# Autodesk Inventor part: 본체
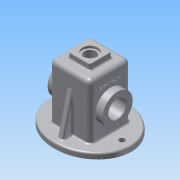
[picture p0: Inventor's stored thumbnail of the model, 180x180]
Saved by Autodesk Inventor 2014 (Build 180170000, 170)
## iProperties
Created: 2017-07
Part Number: 본체
Material: 알루미늄 6061
Document SubType Name: Modeling
Designer: 406-12
Density: 2.71 g/cm^3
Appearance: 알루미늄 - 평지
Mass: 890.222 g
Surface Area: 996.654 cm^2
Volume: 328.495 cm^3
Author: 406-12
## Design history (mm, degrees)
sketch "스케치1"
  geometry: 2 further points; 1 other entity
  constraints: 1 coincident, 2 other
extrude "돌출1" new body sketch "스케치1" distance "d0" = 10; taper "d1" = 0 deg
sketch "스케치2"
  geometry: L1 (0, 10)-(0, 110); L2 (37, 10)-(37, 110); L3 (-37, 10)-(-37, 110); L4 (-74.587, 0)-(99.979, 0); L5 (-37, 110)-(37, 110); L6 (65, 10)-(65, 0) reference; L7 (65, 0)-(-65, 0) reference; L8 (-65, 0)-(-65, 10) reference; L9 (-65, 10)-(65, 10) reference; L10 (-37, 10)-(37, 10); 1 further point
  constraints: 12 end point, 3 parallel, 2 midpoint, 2 point on line
  dimensions: "d2" = 37 distance between parallel lines of L1 L3; "d3" = 37 distance between parallel lines of L2 L1; "d4" = 110 distance between parallel lines of L5 L4
extrude "돌출2" join sketch "스케치2" stored distance "d5" = 74; taper "d6" = 0 deg
sketch "스케치3"
  geometry: L1 (-75, 0)-(-75, 10) reference; L2 (-75, 10)-(-37, 10) reference; L3 (-37, 10)-(-37, 110) reference; L4 (-37, 110)-(37, 110) reference; L5 (37, 110)-(37, 10) reference; L6 (37, 10)-(75, 10) reference; L7 (75, 10)-(75, 0) reference; L8 (75, 0)-(-75, 0) reference; L9 (0, 110)-(0, 120); L10 (-20, 110)-(20, 110); L11 (-19.125, 120)-(19.125, 120); L12 (-20, 110)-(-19.125, 120); L13 (20, 110)-(19.125, 120); 3 further points
  constraints: 10 end point, 2 midpoint, 1 parallel, 1 symmetric about line
  dimensions: "d9" = 10 distance between parallel lines of L4 L11; "d13" = 5 deg angle of L12 L3
extrude "돌출3" join sketch "스케치3" stored distance "d14" = 40; taper "d15" = 0 deg
sketch "스케치4"
  geometry: L1 (-75, 0)-(-75, 10) reference; L2 (-75, 10)-(-37, 10) reference; L3 (-37, 10)-(-37, 110) reference; L4 (-37, 110)-(-20, 110) reference; L5 (-20, 110)-(-19.125, 120) reference; L6 (-19.125, 120)-(19.125, 120) reference; L7 (19.125, 120)-(20, 110) reference; L8 (20, 110)-(37, 110) reference; L9 (37, 110)-(37, 10) reference; L10 (37, 10)-(75, 10) reference; L11 (75, 10)-(75, 0) reference; L12 (75, 0)-(-75, 0) reference; L13 (-32, 0)-(32, 0); L14 (-32, 0)-(-32, 105); L15 (0, 0)-(0, 105); L16 (32, 0)-(32, 105); L17 (-32, 105)-(32, 105); L18 (-32, 0)-(32, 0)
  constraints: 12 end point, 3 parallel, 1 midpoint
extrude "돌출4" cut sketch "스케치4" stored distance "d19" = 64; taper "d20" = 0 deg
node "작업 평면1"
sketch "스케치7"
  geometry: L1 (-10, 48.448)-(0, 48.448) reference; L2 (0, 48.448)-(0, -48.448) reference; L3 (0, -48.448)-(-10, -48.448) reference; L4 (-10, -48.448)-(-10, 48.448) reference; L5 (0, 0)-(-55, 0); C1 r 27.5 at (-55, 0)
  constraints: 2 end point, 1 centre point, 1 coincident
extrude "돌출5" join sketch "스케치7" stored distance "d22" = 64; taper "d23" = 0 deg
sketch "스케치8"
  geometry: L1 (0, 32)-(55, 32); C1 r 27.5 at (55, 32)
  constraints: 2 end point, 1 centre point, 1 coincident
extrude "돌출6" join sketch "스케치8" distance "d24" = 7; taper "d25" = 0 deg
chamfer "모따기1" distance "d26" = 7; stored, may be unused: second distance "d27" = 2, angle "d28" = 135 deg
hole "구멍1" diameter "d31" = 32; stored, may be unused: countersink angle "d35" = 90 deg, drill point angle "d37" = 0 deg; dims "d29" = 10, "d30" = 10, "d32" = 6, "d33" = 4, "d34" = 2, "d36" = 25
sketch "스케치10"
  geometry: 5 further points
hole "구멍2" sketch "스케치10" at (-22.5, 0), (0, -22.5), (22.5, 0), (0, 22.5) diameter "d38" = 3.242; stored, may be unused: countersink angle "d42" = 90 deg, drill point angle "d44" = 118 deg; dims "d39" = 8, "d40" = 4, "d41" = 2, "d43" = 10
sketch "스케치11"
  geometry: 1 further point
hole "구멍3" sketch "스케치11" at (19.125, -20) diameter "d45" = 21; stored, may be unused: countersink angle "d49" = 90 deg, drill point angle "d51" = 118 deg; dims "d46" = 8, "d47" = 28, "d48" = 4, "d50" = 25
sketch "스케치12"
  geometry: L1 (-65, 10)-(-65, 0) reference; L2 (-65, 0)-(-32, 0) reference; L3 (-32, 0)-(-32, 105) reference; L4 (-32, 105)-(-10.5, 105) reference; L5 (-10.5, 105)-(-10.5, 116) reference; L6 (-10.5, 116)-(-14, 116) reference; L7 (-14, 116)-(-14, 120) reference; L8 (-14, 120)-(-20, 120) reference; L9 (-20, 120)-(-20, 110) reference; L10 (-20, 110)-(-37, 110) reference; L11 (-37, 110)-(-37, 10) reference; L12 (-37, 10)-(-65, 10) reference; L13 (65, 0)-(65, 10) reference; L14 (65, 10)-(37, 10) reference; L15 (37, 10)-(37, 110) reference; L16 (37, 110)-(20, 110) reference; L17 (20, 110)-(20, 120) reference; L18 (20, 120)-(14, 120) reference; L19 (14, 120)-(14, 116) reference; L20 (14, 116)-(10.5, 116) reference; L21 (10.5, 116)-(10.5, 105) reference; L22 (10.5, 105)-(32, 105) reference; L23 (32, 105)-(32, 0) reference; L24 (32, 0)-(65, 0) reference; L25 (-65, 0)-(-65, 22.039); L26 (-55, 10)-(-37, 82.194); L27 (-55, 10)-(-37, 10); L28 (-37, 10)-(-37, 82.194); 1 further point
  constraints: 8 end point, 2 point on line
  dimensions: "d54" = 14 deg angle of L1 L26
extrude "돌출7" join sketch "스케치12" stored distance "d55" = 10; taper "d56" = 0 deg
sketch "스케치13"
  geometry: L1 (-10, -56.54)-(-10, -37) reference; L2 (-10, -37)-(-10, 37) reference; L3 (-10, 37)-(-10, 56.54) reference; L4 (-10, 56.54)-(0, 56.54) reference; L5 (0, 56.54)-(0, -56.54) reference; L6 (0, -56.54)-(-10, -56.54) reference; L7 (-10, -37)-(-110, -37) reference; L8 (-110, -37)-(-110, 37) reference; L9 (-110, 37)-(-10, 37) reference; L10 (-110, -20)-(-120, -20) reference; L11 (-120, 20)-(-110, 20) reference; C1 r 16 at (-55, 0) reference; C2 r 27.5 at (-55, 0) reference; 2 further points
  constraints: 1 other
feature "엠보싱1" sketch "스케치13" dims "d13" = 5 deg, "d58" = 0.5, "d59" = 0
fillet "모깎기1" dims "d60" = 8
fillet "모깎기2" dims "d61" = 8
fillet "모깎기3" dims "d62" = 0.5
fillet "모깎기4" dims "d63" = 0.5
chamfer "모따기2" distance "d64" = 1; stored, may be unused: second distance "d65" = 2, angle "d66" = 135 deg
fillet "모깎기5" dims "d67" = 3
fillet "모깎기6" dims "d68" = 3
fillet "모깎기7" dims "d69" = 3
fillet "모깎기8" dims "d70" = 3
fillet "모깎기9" dims "d71" = 3
fillet "모깎기10" dims "d72" = 3
sketch "스케치14"
  geometry: L1 (0, -65)-(0, 103.322); L2 (-58, -72.269)-(-58, 103.322); L3 (58, -72.269)-(58, 103.322); 3 further points; 1 other entity
  constraints: 6 end point, 2 parallel, 2 point on line, 1 vertical alignment, 1 other
  dimensions: "d73" = 58 distance between parallel lines of L2 L1; "d74" = 58 distance between parallel lines of L3 L1
hole "구멍4" sketch "스케치14" at (-58, 0), (58, 0) diameter "d75" = 10; stored, may be unused: countersink angle "d79" = 90 deg, drill point angle "d81" = 118 deg; dims "d76" = 8, "d77" = 4, "d78" = 2, "d80" = 25
fillet "모깎기11" dims "d82" = 3
fillet "모깎기12" dims "d83" = 3
fillet "모깎기13" dims "d84" = 3
node "솔리드1"
mirror "대칭1"
mirror "대칭2"
node "작업 평면2"
node "작업 평면3"
node "절단 모서리 투영1"
node "절단 모서리 투영2"
node "절단 모서리 투영3"
node "절단 모서리 투영4"
node "절단 모서리 투영5"
node "절단 모서리 투영6"
other parameters: "d16" = 32, "d17" = 32, "d18" = 105, "d21" = 13
